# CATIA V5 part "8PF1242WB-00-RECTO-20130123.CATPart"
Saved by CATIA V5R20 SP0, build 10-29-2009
Part number: 8PF1242WB-00-RECTO-20130123
Revision: ANY
Definition: UNKNOWN
Nomenclature: 8PF1242WB-00-RECTO-20130123
Source: Unknown
Bounding box of the stored display mesh (mm): x 1756.119 to 1956.119, y 1406.509 to 1410.509, z 0 to 12
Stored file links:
  C:\Users\Utente\Desktop\IO LAVORO\3D X SITO CF\CUMSA\3D files PF\PF 124200\8PF1242WB-00-RECTO-20130123.CATPart
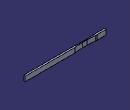
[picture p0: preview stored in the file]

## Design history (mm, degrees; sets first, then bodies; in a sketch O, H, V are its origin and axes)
Body1 "Cortar-Extruir1" (main body)
  Solid1: solid without history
